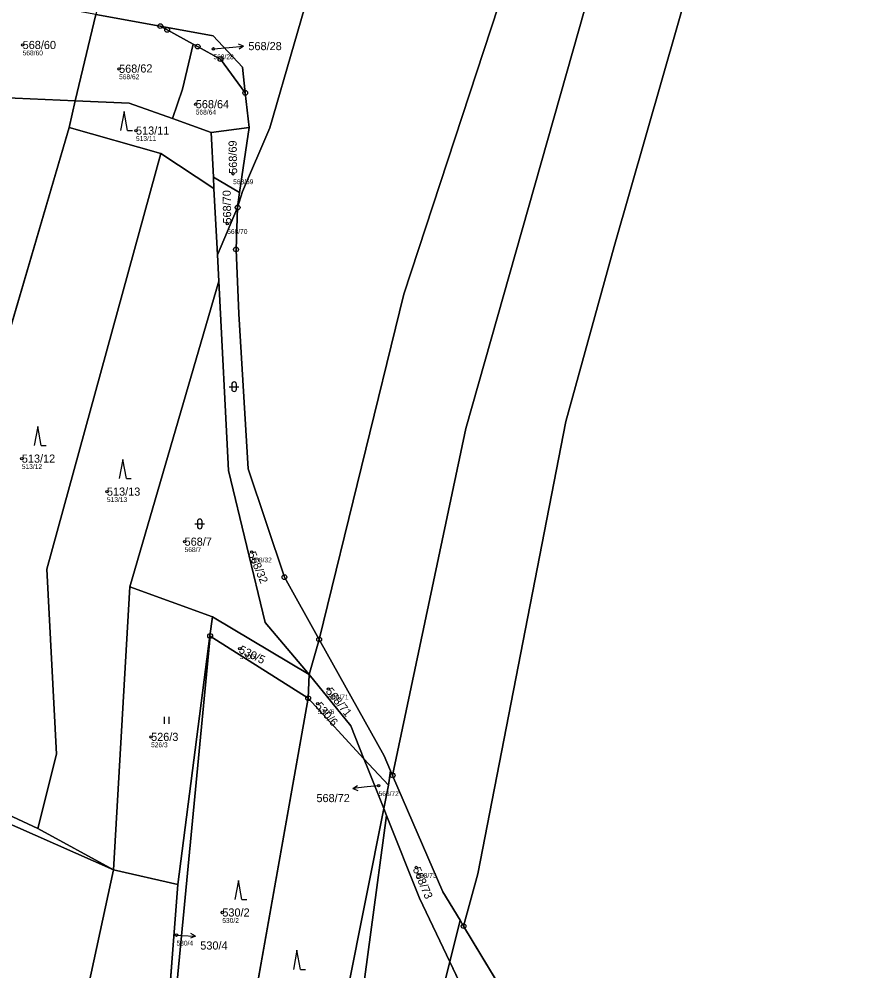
# Model space of a CAD drawing. Extents: x -732749 to -730903, y -1025757 to -1023435.
# Drawn here: x -731726.8 to -731549.4, y -1024539 to -1024340.6 of the extents above; entities that cross this region are included whole.
import ezdxf

# ---------------------------------------------------------------- set-up
doc = ezdxf.new("R2010")
doc.units = 0
for name, color, linetype in [('Definiční body', 7, 'Continuous'), ('Hranice parcel', 7, 'Continuous'), ('Parcelní čísla', 7, 'Continuous'), ('Polygon parcely', 7, 'Continuous'), ('Pop  PČ popisy', 7, 'Continuous'), ('Značky bodu BP', 7, 'Continuous'), ('Značky kultur', 7, 'Continuous')]:
    doc.layers.add(name, color=color, linetype=linetype)

msp = doc.modelspace()

# ---------------------------------------------------------------- linework, layer by layer
at = {"layer": 'Definiční body'}
for centre in [(-731726.06, -1024346), (-731686.28, -1024346.81), (-731705.95, -1024350.98), (-731689.97, -1024358.34), (-731702.43, -1024363.84), (-731682.18, -1024372.85), (-731683.41, -1024383.21), (-731726.23, -1024432.2), (-731708.49, -1024439.08), (-731692.3, -1024449.51), (-731678.34, -1024451.67), (-731680.78, -1024471.81), (-731662.33, -1024480.23), (-731664.54, -1024483.28), (-731699.28, -1024490.19), (-731651.86, -1024500.36), (-731643.99, -1024517.42), (-731684.43, -1024526.79), (-731693.99, -1024531.51)]:
    msp.add_circle(centre, 0.25, dxfattribs=at)
at = {"layer": 'Hranice parcel'}
for p, q in [((-731715.1, -1024357.61), (-731710.83, -1024339.62)), ((-731710.83, -1024339.62), (-731697.36, -1024342.07)), ((-731679.65, -1024355.98), (-731678.81, -1024363.23)), ((-731716.39, -1024363.19), (-731715.1, -1024357.61)), ((-731686.78, -1024364.21), (-731694.82, -1024361.33)), ((-731740.19, -1024444.33), (-731716.39, -1024363.19)), ((-731716.39, -1024363.19), (-731697.25, -1024368.6)), ((-731686.78, -1024364.21), (-731678.81, -1024363.23)), ((-731678.81, -1024363.23), (-731680.84, -1024376.75)), ((-731686.3, -1024373.53), (-731686.78, -1024364.21)), ((-731697.25, -1024368.6), (-731686.18, -1024375.93)), ((-731686.3, -1024373.53), (-731680.84, -1024376.75)), ((-731686.18, -1024375.93), (-731686.3, -1024373.53)), ((-731685.47, -1024389.7), (-731686.18, -1024375.93)), ((-731681.24, -1024379.87), (-731685.47, -1024389.7)), ((-731685.19, -1024395.22), (-731685.47, -1024389.7)), ((-731703.7, -1024458.9), (-731685.19, -1024395.22)), ((-731707.13, -1024517.89), (-731703.7, -1024458.9)), ((-731686.5, -1024465.2), (-731703.7, -1024458.9)), ((-731687.01, -1024469.13), (-731686.5, -1024465.2)), ((-731686.5, -1024465.2), (-731666.3, -1024477.2)), ((-731693.69, -1024520.94), (-731687.01, -1024469.13)), ((-731686.96, -1024469.17), (-731687.01, -1024469.13)), ((-731666.53, -1024482.14), (-731686.96, -1024469.17)), ((-731666.3, -1024477.2), (-731664.24, -1024469.88)), ((-731666.53, -1024482.14), (-731666.3, -1024477.2)), ((-731686.49, -1024594.44), (-731666.53, -1024482.14)), ((-731654.91, -1024494.76), (-731666.53, -1024482.14)), ((-731654.91, -1024494.76), (-731649.82, -1024500.29)), ((-731649.82, -1024500.29), (-731649.35, -1024497.24)), ((-731649.35, -1024497.24), (-731648.93, -1024498.21)), ((-731650.78, -1024505.11), (-731649.82, -1024500.29)), ((-731743.44, -1024501.87), (-731707.13, -1024517.89)), ((-731656.73, -1024555.17), (-731650.19, -1024506.59)), ((-731650.19, -1024506.59), (-731650.78, -1024505.11)), ((-731722.91, -1024509.3), (-731707.13, -1024517.89)), ((-731707.13, -1024517.89), (-731693.69, -1024520.94)), ((-731696.14, -1024552.61), (-731693.69, -1024520.94)), ((-731637.02, -1024537.04), (-731634.87, -1024528.39)), ((-731634.87, -1024528.39), (-731634.13, -1024529.62)), ((-731634.13, -1024529.62), (-731620.06, -1024552.99)), ((-731639.82, -1024548.26), (-731637.02, -1024537.04)), ((-731630.06, -1024551.69), (-731637.02, -1024537.04))]:
    msp.add_line(p, q, dxfattribs=at)
for points in [[(-731591.95, -1024203.79), (-731617.38, -1024296.29), (-731626.82, -1024337.82), (-731646.57, -1024397.91), (-731664.24, -1024469.88)], [(-731570.87, -1024204.37), (-731633.63, -1024425.93), (-731648.93, -1024498.21)], [(-731634.3, -1024206.79), (-731645.91, -1024251.08), (-731664.41, -1024328.19), (-731674.52, -1024363.29), (-731680.24, -1024376.54), (-731681.24, -1024379.87)], [(-731549.41, -1024205.75), (-731565.96, -1024259.66), (-731602.73, -1024388.01), (-731612.84, -1024424.44), (-731631.17, -1024518.71), (-731634.13, -1024529.62)], [(-731697.36, -1024342.07), (-731686.37, -1024344.07), (-731680.26, -1024350.64), (-731679.65, -1024355.98)], [(-731697.36, -1024342.07), (-731695.93, -1024342.86), (-731690.52, -1024345.82)], [(-731694.82, -1024361.33), (-731692.76, -1024355.18), (-731690.52, -1024345.82)], [(-731690.52, -1024345.82), (-731689.58, -1024346.33), (-731684.82, -1024348.93), (-731679.65, -1024355.98)], [(-731715.1, -1024357.61), (-731730.73, -1024356.93), (-731732.05, -1024357.71)], [(-731694.82, -1024361.33), (-731703.86, -1024358.1), (-731715.1, -1024357.61)], [(-731722.91, -1024509.3), (-731719.02, -1024493.81), (-731721.04, -1024455.23), (-731697.25, -1024368.6)], [(-731680.84, -1024376.75), (-731681.21, -1024379.22), (-731681.24, -1024379.87)], [(-731681.24, -1024379.87), (-731681.58, -1024388.61), (-731681, -1024402.03), (-731679.07, -1024434.31), (-731671.48, -1024456.9), (-731664.24, -1024469.88)], [(-731666.3, -1024477.2), (-731675.52, -1024466.37), (-731683.16, -1024434.69), (-731685.19, -1024395.22)], [(-731740.19, -1024444.33), (-731737.87, -1024476.57), (-731737.29, -1024481.37), (-731741.71, -1024500.51), (-731722.91, -1024509.3)], [(-731686.96, -1024469.17), (-731695.35, -1024557.09), (-731696.77, -1024562.48)], [(-731664.24, -1024469.88), (-731650.68, -1024494.17), (-731649.35, -1024497.24)], [(-731654.91, -1024494.76), (-731657.64, -1024487.92), (-731666.3, -1024477.2)], [(-731650.78, -1024505.11), (-731654.37, -1024496.11), (-731654.91, -1024494.76)], [(-731648.93, -1024498.21), (-731638.45, -1024522.46), (-731634.87, -1024528.39)], [(-731673.09, -1024610.86), (-731658.36, -1024543.11), (-731650.78, -1024505.11)], [(-731637.02, -1024537.04), (-731643.32, -1024523.8), (-731650.19, -1024506.59)], [(-731734.05, -1024633.47), (-731713.45, -1024547.12), (-731707.13, -1024517.89)]]:
    msp.add_lwpolyline(points, dxfattribs=at)
at = {"layer": 'Polygon parcely'}
for points in [[(-731681.24, -1024379.87), (-731681.58, -1024388.61), (-731681, -1024402.03), (-731679.07, -1024434.31), (-731671.48, -1024456.9), (-731664.24, -1024469.88), (-731646.57, -1024397.91), (-731626.82, -1024337.82), (-731617.38, -1024296.29), (-731591.95, -1024203.79), (-731620.23, -1024203), (-731634.3, -1024206.79), (-731645.91, -1024251.08), (-731664.41, -1024328.19), (-731674.52, -1024363.29), (-731680.24, -1024376.54)], [(-731664.24, -1024469.88), (-731650.68, -1024494.17), (-731649.35, -1024497.24), (-731648.93, -1024498.21), (-731633.63, -1024425.93), (-731570.87, -1024204.37), (-731591.95, -1024203.79), (-731617.38, -1024296.29), (-731626.82, -1024337.82), (-731646.57, -1024397.91)], [(-731633.63, -1024425.93), (-731648.93, -1024498.21), (-731638.45, -1024522.46), (-731634.87, -1024528.39), (-731634.13, -1024529.62), (-731631.17, -1024518.71), (-731612.84, -1024424.44), (-731602.73, -1024388.01), (-731565.96, -1024259.66), (-731549.41, -1024205.75), (-731550.27, -1024205.65), (-731557.95, -1024204.73), (-731570.87, -1024204.37)], [(-731686.67, -1024228.22), (-731702.25, -1024302.71), (-731710.83, -1024339.62), (-731697.36, -1024342.07), (-731686.37, -1024344.07), (-731680.26, -1024350.64), (-731679.65, -1024355.98), (-731678.81, -1024363.23), (-731680.84, -1024376.75), (-731681.21, -1024379.22), (-731681.24, -1024379.87), (-731680.24, -1024376.54), (-731674.52, -1024363.29), (-731664.41, -1024328.19), (-731645.91, -1024251.08), (-731634.3, -1024206.79), (-731652.83, -1024211.78), (-731661.87, -1024211.8), (-731683.09, -1024211.86)], [(-731715.1, -1024357.61), (-731710.83, -1024339.62), (-731715.01, -1024338.86), (-731730.32, -1024334.42), (-731735.44, -1024356.95), (-731732.05, -1024357.71), (-731730.73, -1024356.93)], [(-731690.52, -1024345.82), (-731695.93, -1024342.86), (-731697.36, -1024342.07), (-731710.83, -1024339.62), (-731715.1, -1024357.61), (-731703.86, -1024358.1), (-731694.82, -1024361.33), (-731692.76, -1024355.18)], [(-731697.36, -1024342.07), (-731695.93, -1024342.86), (-731690.52, -1024345.82), (-731689.58, -1024346.33), (-731684.82, -1024348.93), (-731679.65, -1024355.98), (-731680.26, -1024350.64), (-731686.37, -1024344.07)], [(-731678.81, -1024363.23), (-731679.65, -1024355.98), (-731684.82, -1024348.93), (-731689.58, -1024346.33), (-731690.52, -1024345.82), (-731692.76, -1024355.18), (-731694.82, -1024361.33), (-731686.78, -1024364.21)], [(-731716.39, -1024363.19), (-731715.1, -1024357.61), (-731730.73, -1024356.93), (-731732.05, -1024357.71), (-731736.17, -1024360.15), (-731742.91, -1024386.11), (-731745.08, -1024393.87), (-731753.18, -1024422.6), (-731758.46, -1024437.59), (-731740.19, -1024444.33)], [(-731686.18, -1024375.93), (-731686.3, -1024373.53), (-731686.78, -1024364.21), (-731694.82, -1024361.33), (-731703.86, -1024358.1), (-731715.1, -1024357.61), (-731716.39, -1024363.19), (-731697.25, -1024368.6)], [(-731721.04, -1024455.23), (-731697.25, -1024368.6), (-731716.39, -1024363.19), (-731740.19, -1024444.33), (-731737.87, -1024476.57), (-731737.29, -1024481.37), (-731741.71, -1024500.51), (-731722.91, -1024509.3), (-731719.02, -1024493.81)], [(-731680.84, -1024376.75), (-731678.81, -1024363.23), (-731686.78, -1024364.21), (-731686.3, -1024373.53)], [(-731685.47, -1024389.7), (-731686.18, -1024375.93), (-731697.25, -1024368.6), (-731721.04, -1024455.23), (-731719.02, -1024493.81), (-731722.91, -1024509.3), (-731707.13, -1024517.89), (-731703.7, -1024458.9), (-731685.19, -1024395.22)], [(-731686.3, -1024373.53), (-731686.18, -1024375.93), (-731685.47, -1024389.7), (-731681.24, -1024379.87), (-731681.21, -1024379.22), (-731680.84, -1024376.75)], [(-731681.24, -1024379.87), (-731685.47, -1024389.7), (-731685.19, -1024395.22), (-731683.16, -1024434.69), (-731675.52, -1024466.37), (-731666.3, -1024477.2), (-731664.24, -1024469.88), (-731671.48, -1024456.9), (-731679.07, -1024434.31), (-731681, -1024402.03), (-731681.58, -1024388.61)], [(-731666.3, -1024477.2), (-731675.52, -1024466.37), (-731683.16, -1024434.69), (-731685.19, -1024395.22), (-731703.7, -1024458.9), (-731686.5, -1024465.2)], [(-731740.19, -1024444.33), (-731744.46, -1024454.32), (-731746.1, -1024457.98), (-731748.22, -1024462.58), (-731741.03, -1024470.21), (-731739.58, -1024471.75), (-731739.81, -1024473), (-731743, -1024490.66), (-731743.44, -1024501.87), (-731707.13, -1024517.89), (-731722.91, -1024509.3), (-731741.71, -1024500.51), (-731737.29, -1024481.37), (-731737.87, -1024476.57)], [(-731707.13, -1024517.89), (-731693.69, -1024520.94), (-731687.01, -1024469.13), (-731686.5, -1024465.2), (-731703.7, -1024458.9)], [(-731666.3, -1024477.2), (-731686.5, -1024465.2), (-731687.01, -1024469.13), (-731686.96, -1024469.17), (-731666.53, -1024482.14)], [(-731687.01, -1024469.13), (-731693.69, -1024520.94), (-731696.14, -1024552.61), (-731697.08, -1024561.67), (-731696.77, -1024562.48), (-731695.35, -1024557.09), (-731686.96, -1024469.17)], [(-731695.35, -1024557.09), (-731696.77, -1024562.48), (-731686.49, -1024594.44), (-731666.53, -1024482.14), (-731686.96, -1024469.17)], [(-731649.82, -1024500.29), (-731649.35, -1024497.24), (-731650.68, -1024494.17), (-731664.24, -1024469.88), (-731666.3, -1024477.2), (-731657.64, -1024487.92), (-731654.91, -1024494.76)], [(-731666.3, -1024477.2), (-731666.53, -1024482.14), (-731654.91, -1024494.76), (-731657.64, -1024487.92)], [(-731658.36, -1024543.11), (-731650.78, -1024505.11), (-731654.37, -1024496.11), (-731654.91, -1024494.76), (-731666.53, -1024482.14), (-731686.49, -1024594.44), (-731673.09, -1024610.86)], [(-731649.82, -1024500.29), (-731654.91, -1024494.76), (-731654.37, -1024496.11), (-731650.78, -1024505.11)], [(-731707.13, -1024517.89), (-731743.44, -1024501.87), (-731759.7, -1024496.71), (-731787.4, -1024607.01), (-731752.45, -1024614.47), (-731732.6, -1024618.66), (-731734.11, -1024625.8), (-731735.24, -1024629.79), (-731736, -1024632.96), (-731734.05, -1024633.47), (-731713.45, -1024547.12)], [(-731634.87, -1024528.39), (-731638.45, -1024522.46), (-731648.93, -1024498.21), (-731649.35, -1024497.24), (-731649.82, -1024500.29), (-731650.78, -1024505.11), (-731650.19, -1024506.59), (-731643.32, -1024523.8), (-731637.02, -1024537.04)], [(-731656.73, -1024555.17), (-731650.19, -1024506.59), (-731650.78, -1024505.11), (-731658.36, -1024543.11), (-731673.09, -1024610.86), (-731670.56, -1024613.95), (-731664.27, -1024586.86)], [(-731637.02, -1024537.04), (-731643.32, -1024523.8), (-731650.19, -1024506.59), (-731656.73, -1024555.17), (-731653.71, -1024557.46), (-731645.4, -1024563.74), (-731648.54, -1024585.48), (-731648.95, -1024588.3), (-731645.79, -1024574.11), (-731639.82, -1024548.26)], [(-731693.69, -1024520.94), (-731707.13, -1024517.89), (-731713.45, -1024547.12), (-731734.05, -1024633.47), (-731716.63, -1024638.06), (-731716.24, -1024638.26), (-731697.08, -1024561.67), (-731696.14, -1024552.61)], [(-731620.06, -1024552.99), (-731634.13, -1024529.62), (-731634.87, -1024528.39), (-731637.02, -1024537.04), (-731630.06, -1024551.69), (-731622.04, -1024562.41)], [(-731630.06, -1024551.69), (-731637.02, -1024537.04), (-731639.82, -1024548.26), (-731622.62, -1024565.19), (-731622.04, -1024562.41)]]:
    msp.add_lwpolyline(points, close=True, dxfattribs=at)
msp.add_lwpolyline([(-731565.96, -1024259.66), (-731602.73, -1024388.01), (-731612.84, -1024424.44), (-731631.17, -1024518.71), (-731634.13, -1024529.62), (-731620.06, -1024552.99)], dxfattribs=at)
at = {"layer": 'Pop  PČ popisy'}
for p, q in [((-731680, -1024346.25), (-731681.04, -1024345.84)), ((-731686.28, -1024346.81), (-731682.99, -1024346.51)), ((-731682.99, -1024346.51), (-731680, -1024346.25)), ((-731680, -1024346.25), (-731680.95, -1024346.84)), ((-731657.2, -1024500.94), (-731656.26, -1024500.34)), ((-731654.22, -1024500.63), (-731657.2, -1024500.94)), ((-731651.86, -1024500.36), (-731654.22, -1024500.63)), ((-731657.2, -1024500.94), (-731656.16, -1024501.34)), ((-731693.99, -1024531.51), (-731693.03, -1024531.55)), ((-731693.03, -1024531.55), (-731690.03, -1024531.71)), ((-731690.03, -1024531.71), (-731691.06, -1024532.16)), ((-731690.03, -1024531.71), (-731691.01, -1024531.16))]:
    msp.add_line(p, q, dxfattribs=at)
at = {"layer": 'Značky bodu BP'}
for centre, radius in [((-731697.36, -1024342.07), 0.5), ((-731697.36, -1024342.07), 0.0303), ((-731695.93, -1024342.86), 0.5), ((-731695.93, -1024342.86), 0.0303), ((-731689.58, -1024346.33), 0.5), ((-731689.58, -1024346.33), 0.0303), ((-731684.82, -1024348.93), 0.5), ((-731684.82, -1024348.93), 0.0303), ((-731679.65, -1024355.98), 0.5), ((-731679.65, -1024355.98), 0.0303), ((-731681.24, -1024379.87), 0.5), ((-731681.24, -1024379.87), 0.0303), ((-731681.58, -1024388.61), 0.5), ((-731681.58, -1024388.61), 0.0303), ((-731671.48, -1024456.9), 0.5), ((-731671.48, -1024456.9), 0.0303), ((-731686.96, -1024469.17), 0.5), ((-731686.96, -1024469.17), 0.0303), ((-731664.24, -1024469.88), 0.5), ((-731664.24, -1024469.88), 0.0303), ((-731666.53, -1024482.14), 0.5), ((-731666.53, -1024482.14), 0.0303), ((-731648.93, -1024498.21), 0.5), ((-731648.93, -1024498.21), 0.0303), ((-731634.13, -1024529.62), 0.5), ((-731634.13, -1024529.62), 0.0303)]:
    msp.add_circle(centre, radius, dxfattribs=at)
at = {"layer": 'Značky kultur'}
for p, q in [((-731704.93, -1024359.84), (-731705.68, -1024363.84)), ((-731704.18, -1024363.84), (-731704.93, -1024359.84)), ((-731704.18, -1024363.84), (-731703.18, -1024363.84)), ((-731682.98, -1024417.21), (-731680.98, -1024417.21)), ((-731682.48, -1024416.71), (-731682.48, -1024417.71)), ((-731681.48, -1024417.71), (-731681.48, -1024416.71)), ((-731722.92, -1024425.5), (-731723.67, -1024429.5)), ((-731722.17, -1024429.5), (-731722.92, -1024425.5)), ((-731722.17, -1024429.5), (-731721.17, -1024429.5)), ((-731705.17, -1024432.38), (-731705.92, -1024436.38)), ((-731704.42, -1024436.38), (-731705.17, -1024432.38)), ((-731704.42, -1024436.38), (-731703.42, -1024436.38)), ((-731690.14, -1024445.81), (-731688.14, -1024445.81)), ((-731689.64, -1024445.31), (-731689.64, -1024446.31)), ((-731688.64, -1024446.31), (-731688.64, -1024445.31)), ((-731696.48, -1024487.49), (-731696.48, -1024485.99)), ((-731695.48, -1024487.49), (-731695.48, -1024485.99)), ((-731681.09, -1024520.09), (-731681.84, -1024524.09)), ((-731680.34, -1024524.09), (-731681.09, -1024520.09)), ((-731680.34, -1024524.09), (-731679.34, -1024524.09)), ((-731668.87, -1024534.64), (-731669.62, -1024538.64)), ((-731668.12, -1024538.64), (-731668.87, -1024534.64)), ((-731668.12, -1024538.64), (-731667.12, -1024538.64))]:
    msp.add_line(p, q, dxfattribs=at)
for centre, start, end in [((-731681.98, -1024416.71), 0, 180), ((-731681.98, -1024417.71), 180, 359.9879), ((-731689.14, -1024445.31), 0, 180), ((-731689.14, -1024446.31), 180, 359.9879)]:
    msp.add_arc(centre, 0.5, start, end, dxfattribs=at)

# ---------------------------------------------------------------- texts
at = {"layer": 'Definiční body'}
for s, p in [('568/60', (-731726.06, -1024348.16)), ('568/28', (-731686.28, -1024348.97)), ('568/62', (-731705.95, -1024353.14)), ('568/64', (-731689.97, -1024360.5)), ('513/11', (-731702.43, -1024366)), ('568/69', (-731682.18, -1024375.01)), ('568/70', (-731683.41, -1024385.37)), ('513/12', (-731726.23, -1024434.36)), ('513/13', (-731708.49, -1024441.24)), ('568/7', (-731692.3, -1024451.67)), ('568/32', (-731678.34, -1024453.83)), ('530/5', (-731680.78, -1024473.97)), ('568/71', (-731662.33, -1024482.39)), ('530/6', (-731664.54, -1024485.44)), ('526/3', (-731699.28, -1024492.35)), ('568/72', (-731651.86, -1024502.52)), ('568/73', (-731643.99, -1024519.58)), ('530/2', (-731684.43, -1024528.95)), ('530/4', (-731693.99, -1024533.67))]:
    msp.add_text(s, height=1, dxfattribs=at).set_placement(p)
at = {"layer": 'Parcelní čísla'}
for s, p in [('568/60', (-731726.06, -1024346.85)), ('568/28', (-731679, -1024347.08)), ('568/64', (-731689.97, -1024359.19)), ('513/11', (-731702.43, -1024364.69)), ('513/12', (-731726.23, -1024433.05)), ('513/13', (-731708.49, -1024439.93)), ('568/7', (-731692.3, -1024450.36)), ('526/3', (-731699.28, -1024491.04)), ('568/72', (-731664.81, -1024503.79)), ('530/2', (-731684.43, -1024527.64)), ('530/4', (-731689.03, -1024534.52))]:
    msp.add_text(s, height=1.7, dxfattribs=at).set_placement(p)
for s, rotation, p in [('568/62', 1, (-731705.94, -1024351.83)), ('568/69', 91, (-731681.33, -1024372.84)), ('568/70', 91, (-731682.56, -1024383.2)), ('568/32', 293, (-731679.12, -1024452)), ('530/5', 334, (-731681.15, -1024472.57)), ('568/71', 309, (-731662.99, -1024480.76)), ('530/6', 311, (-731665.18, -1024483.84)), ('568/73', 293, (-731644.77, -1024517.75))]:
    msp.add_text(s, height=1.7, rotation=rotation, dxfattribs=at).set_placement(p)

doc.saveas('drawing.dxf')
